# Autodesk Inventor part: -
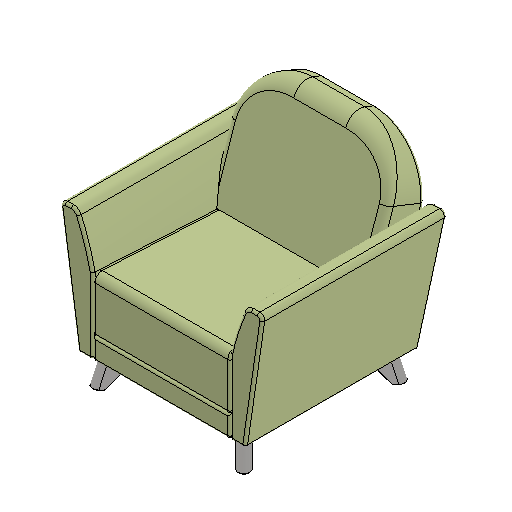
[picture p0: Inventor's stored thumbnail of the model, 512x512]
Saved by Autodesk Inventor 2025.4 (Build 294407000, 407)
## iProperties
Created: 2026-05
Part Number: -
Material: Generic
Description: ARMCHAIR
Document SubType Name: Modeling
Designer: Brian.Thangei
Density: 1 g/cm^3
Appearance: Default
Project: HENLEY
Sending System: SolidWorks 2026
Preprocessor: SwSTEP 2.0
Title: Henley Armchiar.STEP
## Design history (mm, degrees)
feature "NONE"
feature "NONE:1"
feature "NONE:2"
feature "NONE:3"
feature "NONE:4"
feature "NONE:5"
feature "NONE:6"
feature "NONE:7"
feature "NONE:8"
workplane "Work Plane1"
workplane "Work Plane2"
workplane "Work Plane3"
workplane "Work Plane4"
workplane "Work Plane5"
node "Direct Edit1"
node "SEAT"
node "BASE"
node "ARM"
node "FOOT"
node "ARM2"
node "FOOT2"
node "FOOT3"
node "FOOT4"
node "BACK"
move_body "Move1" dims "d0" = 10
move_body "Move2" dims "d3" = -10
other parameters: "d1" = 0, "d2" = 0, "d4" = 0, "d5" = 0
